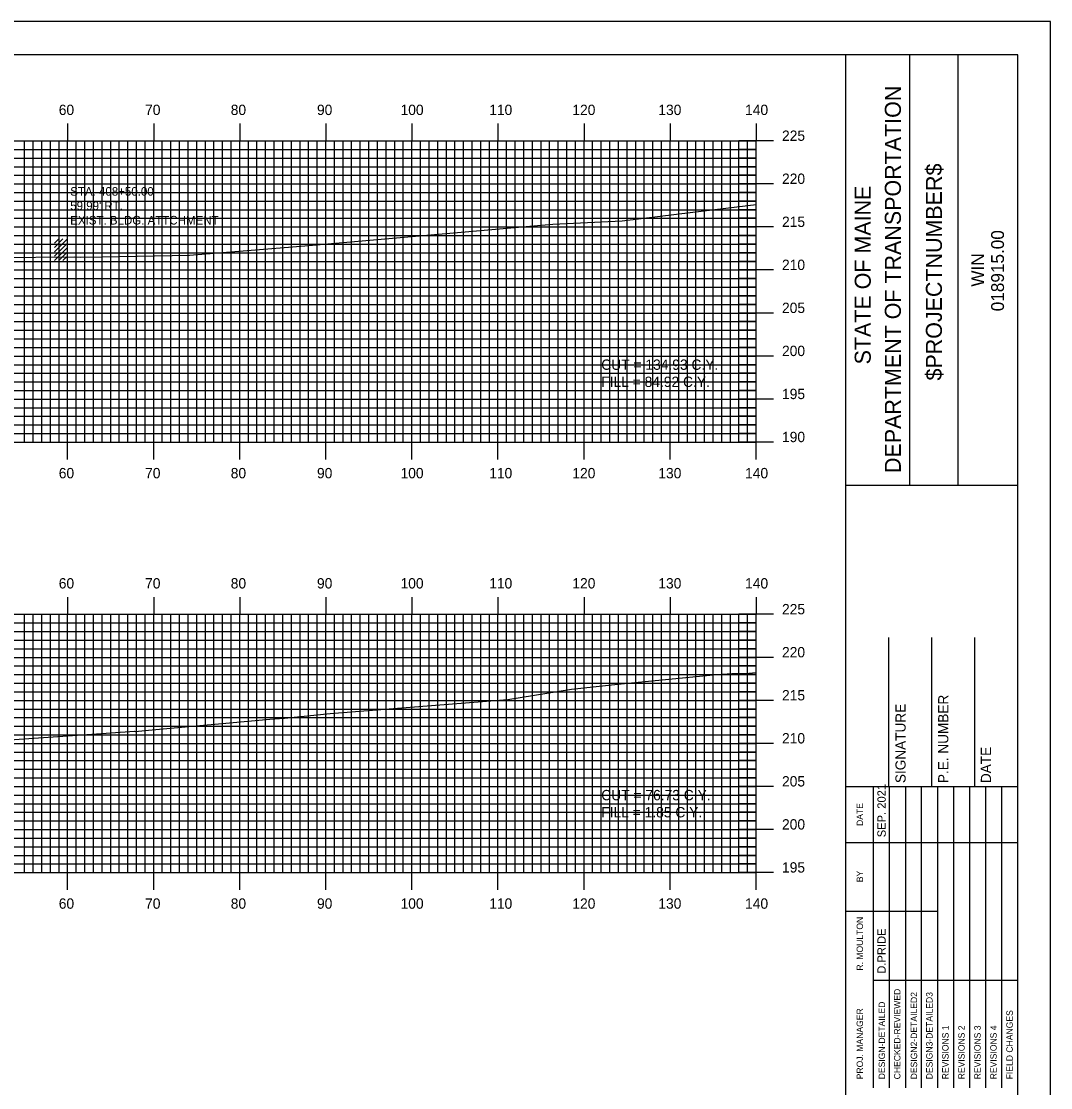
# Model space of a CAD drawing. Extents: x 852529 to 852872, y 364785 to 365005.
# Drawn here: x 852749.3 to 852868.9, y 364881.2 to 365005.1 of the extents above; entities that cross this region are included whole.
import ezdxf

# ---------------------------------------------------------------- set-up
doc = ezdxf.new("R2010")
doc.units = 0
for name, color, linetype in [('BORDER', 7, 'Continuous'), ('D_Text_Monospaced', 7, 'Continuous'), ('D_Text_Standard', 7, 'Continuous'), ('H_V ANNOTATION', 7, 'Continuous'), ('M_Buildings_Attachments', 7, 'Continuous'), ('MAJOR', 7, 'Continuous'), ('MINOR', 7, 'Continuous'), ('PLOT BOUNDARY', 7, 'Continuous'), ('S_Roadway_Centerline', 7, 'Continuous')]:
    doc.layers.add(name, color=color, linetype=linetype)

msp = doc.modelspace()

# ---------------------------------------------------------------- linework, layer by layer
at = {"layer": 'BORDER'}
for p, q in [((852845.13, 364791.23), (852845.13, 365001.23)), ((852852.59, 364951.23), (852852.59, 365001.23)), ((852858.18, 364951.23), (852858.18, 365001.23)), ((852845.13, 364951.22), (852865.13, 364951.22)), ((852850.13, 364916.24), (852850.13, 364933.53)), ((852855.13, 364916.24), (852855.13, 364933.53)), ((852860.13, 364916.24), (852860.13, 364933.53)), ((852845.13, 364916.24), (852865.13, 364916.24))]:
    msp.add_line(p, q, dxfattribs=at)
msp.add_lwpolyline([(852545.13, 364791.23), (852865.13, 364791.23), (852865.13, 365001.23), (852545.13, 365001.23)], close=True, dxfattribs=at)
for points in [[(852848.36, 364909.74), (852848.36, 364916.24)], [(852850.23, 364881.24), (852850.23, 364916.24)], [(852852.09, 364916.24), (852852.09, 364881.24)], [(852853.95, 364881.24), (852853.95, 364916.24)], [(852855.82, 364881.24), (852855.82, 364916.24)], [(852857.68, 364881.24), (852857.68, 364916.24)], [(852859.54, 364881.24), (852859.54, 364916.24)], [(852861.41, 364881.24), (852861.41, 364916.24)], [(852863.27, 364881.24), (852863.27, 364916.24)], [(852848.36, 364881.24), (852848.36, 364914.83)], [(852845.13, 364909.74), (852865.13, 364909.74)], [(852845.13, 364901.74), (852848.36, 364901.74)], [(852848.36, 364901.74), (852855.81, 364901.74)], [(852848.36, 364893.74), (852865.13, 364893.74)]]:
    msp.add_lwpolyline(points, dxfattribs=at)
at = {"layer": 'M_Buildings_Attachments'}
for p, q in [((852753.21, 364978.34), (852754.72, 364979.85)), ((852753.21, 364978.84), (852754.19, 364979.85)), ((852753.21, 364979.33), (852753.7, 364979.85)), ((852753.21, 364977.85), (852754.72, 364979.33)), ((852754.72, 364977.33), (852754.72, 364979.85)), ((852753.21, 364977.33), (852754.72, 364978.84)), ((852753.7, 364977.33), (852754.72, 364978.34)), ((852754.19, 364977.33), (852754.72, 364977.85))]:
    msp.add_line(p, q, dxfattribs=at)
at = {"layer": 'MAJOR'}
for p, q in [((852754.73, 364993.24), (852754.73, 364991.23)), ((852764.73, 364993.24), (852764.73, 364991.23)), ((852774.73, 364993.24), (852774.73, 364991.23)), ((852784.73, 364993.24), (852784.73, 364991.23)), ((852794.73, 364993.24), (852794.73, 364991.23)), ((852804.73, 364993.24), (852804.73, 364991.23)), ((852814.73, 364993.24), (852814.73, 364991.23)), ((852824.73, 364993.24), (852824.73, 364991.23)), ((852834.73, 364993.24), (852834.73, 364991.23)), ((852554.73, 364991.23), (852834.73, 364991.23)), ((852554.73, 364991.23), (852834.73, 364991.23)), ((852754.73, 364956.23), (852754.73, 364991.23)), ((852764.73, 364956.23), (852764.73, 364991.23)), ((852774.73, 364956.23), (852774.73, 364991.23)), ((852784.73, 364956.23), (852784.73, 364991.23)), ((852794.73, 364956.23), (852794.73, 364991.23)), ((852804.73, 364956.23), (852804.73, 364991.23)), ((852814.73, 364956.23), (852814.73, 364991.23)), ((852824.73, 364956.23), (852824.73, 364991.23)), ((852836.73, 364991.23), (852832.73, 364991.23)), ((852834.73, 364956.23), (852834.73, 364991.23)), ((852834.73, 364956.23), (852834.73, 364991.23)), ((852554.73, 364986.23), (852834.73, 364986.23)), ((852836.73, 364986.23), (852832.73, 364986.23)), ((852554.73, 364981.23), (852834.73, 364981.23)), ((852836.73, 364981.23), (852832.73, 364981.23)), ((852554.73, 364976.23), (852834.73, 364976.23)), ((852836.73, 364976.23), (852832.73, 364976.23)), ((852554.73, 364971.23), (852834.73, 364971.23)), ((852836.73, 364971.23), (852832.73, 364971.23)), ((852554.73, 364966.23), (852834.73, 364966.23)), ((852836.73, 364966.23), (852832.73, 364966.23)), ((852554.73, 364961.23), (852834.73, 364961.23)), ((852836.73, 364961.23), (852832.73, 364961.23)), ((852554.73, 364956.23), (852834.73, 364956.23)), ((852554.73, 364956.23), (852834.73, 364956.23)), ((852754.73, 364954.23), (852754.73, 364956.23)), ((852764.73, 364954.23), (852764.73, 364956.23)), ((852774.73, 364954.23), (852774.73, 364956.23)), ((852784.73, 364954.23), (852784.73, 364956.23)), ((852794.73, 364954.23), (852794.73, 364956.23)), ((852804.73, 364954.23), (852804.73, 364956.23)), ((852814.73, 364954.23), (852814.73, 364956.23)), ((852824.73, 364954.23), (852824.73, 364956.23)), ((852836.73, 364956.23), (852832.73, 364956.23)), ((852834.73, 364954.23), (852834.73, 364956.23)), ((852754.73, 364938.24), (852754.73, 364936.23)), ((852764.73, 364938.24), (852764.73, 364936.23)), ((852774.73, 364938.24), (852774.73, 364936.23)), ((852784.73, 364938.24), (852784.73, 364936.23)), ((852794.73, 364938.24), (852794.73, 364936.23)), ((852804.73, 364938.24), (852804.73, 364936.23)), ((852814.73, 364938.24), (852814.73, 364936.23)), ((852824.73, 364938.24), (852824.73, 364936.23)), ((852834.73, 364938.24), (852834.73, 364936.23)), ((852554.73, 364936.23), (852834.73, 364936.23)), ((852554.73, 364936.23), (852834.73, 364936.23)), ((852754.73, 364906.23), (852754.73, 364936.23)), ((852764.73, 364906.23), (852764.73, 364936.23)), ((852774.73, 364906.23), (852774.73, 364936.23)), ((852784.73, 364906.23), (852784.73, 364936.23)), ((852794.73, 364906.23), (852794.73, 364936.23)), ((852804.73, 364906.23), (852804.73, 364936.23)), ((852814.73, 364906.23), (852814.73, 364936.23)), ((852824.73, 364906.23), (852824.73, 364936.23)), ((852836.73, 364936.23), (852832.73, 364936.23)), ((852834.73, 364906.23), (852834.73, 364936.23)), ((852834.73, 364906.23), (852834.73, 364936.23)), ((852554.73, 364931.23), (852834.73, 364931.23)), ((852836.73, 364931.23), (852832.73, 364931.23)), ((852554.73, 364926.23), (852834.73, 364926.23)), ((852836.73, 364926.23), (852832.73, 364926.23)), ((852554.73, 364921.23), (852834.73, 364921.23)), ((852836.73, 364921.23), (852832.73, 364921.23)), ((852554.73, 364916.23), (852834.73, 364916.23)), ((852836.73, 364916.23), (852832.73, 364916.23)), ((852554.73, 364911.23), (852834.73, 364911.23)), ((852836.73, 364911.23), (852832.73, 364911.23)), ((852554.73, 364906.23), (852834.73, 364906.23)), ((852554.73, 364906.23), (852834.73, 364906.23)), ((852754.73, 364904.23), (852754.73, 364906.23)), ((852764.73, 364904.23), (852764.73, 364906.23)), ((852774.73, 364904.23), (852774.73, 364906.23)), ((852784.73, 364904.23), (852784.73, 364906.23)), ((852794.73, 364904.23), (852794.73, 364906.23)), ((852804.73, 364904.23), (852804.73, 364906.23)), ((852814.73, 364904.23), (852814.73, 364906.23)), ((852824.73, 364904.23), (852824.73, 364906.23)), ((852836.73, 364906.23), (852832.73, 364906.23)), ((852834.73, 364904.23), (852834.73, 364906.23))]:
    msp.add_line(p, q, dxfattribs=at)
at = {"layer": 'MINOR'}
for p, q in [((852554.73, 364990.23), (852834.73, 364990.23)), ((852749.73, 364956.23), (852749.73, 364991.23)), ((852750.73, 364956.23), (852750.73, 364991.23)), ((852751.73, 364956.23), (852751.73, 364991.23)), ((852752.73, 364956.23), (852752.73, 364991.23)), ((852753.73, 364956.23), (852753.73, 364991.23)), ((852755.73, 364956.23), (852755.73, 364991.23)), ((852756.73, 364956.23), (852756.73, 364991.23)), ((852757.73, 364956.23), (852757.73, 364991.23)), ((852758.73, 364956.23), (852758.73, 364991.23)), ((852759.73, 364956.23), (852759.73, 364991.23)), ((852760.73, 364956.23), (852760.73, 364991.23)), ((852761.73, 364956.23), (852761.73, 364991.23)), ((852762.73, 364956.23), (852762.73, 364991.23)), ((852763.73, 364956.23), (852763.73, 364991.23)), ((852765.73, 364956.23), (852765.73, 364991.23)), ((852766.73, 364956.23), (852766.73, 364991.23)), ((852767.73, 364956.23), (852767.73, 364991.23)), ((852768.73, 364956.23), (852768.73, 364991.23)), ((852769.73, 364956.23), (852769.73, 364991.23)), ((852770.73, 364956.23), (852770.73, 364991.23)), ((852771.73, 364956.23), (852771.73, 364991.23)), ((852772.73, 364956.23), (852772.73, 364991.23)), ((852773.73, 364956.23), (852773.73, 364991.23)), ((852775.73, 364956.23), (852775.73, 364991.23)), ((852776.73, 364956.23), (852776.73, 364991.23)), ((852777.73, 364956.23), (852777.73, 364991.23)), ((852778.73, 364956.23), (852778.73, 364991.23)), ((852779.73, 364956.23), (852779.73, 364991.23)), ((852780.73, 364956.23), (852780.73, 364991.23)), ((852781.73, 364956.23), (852781.73, 364991.23)), ((852782.73, 364956.23), (852782.73, 364991.23)), ((852783.73, 364956.23), (852783.73, 364991.23)), ((852785.73, 364956.23), (852785.73, 364991.23)), ((852786.73, 364956.23), (852786.73, 364991.23)), ((852787.73, 364956.23), (852787.73, 364991.23)), ((852788.73, 364956.23), (852788.73, 364991.23)), ((852789.73, 364956.23), (852789.73, 364991.23)), ((852790.73, 364956.23), (852790.73, 364991.23)), ((852791.73, 364956.23), (852791.73, 364991.23)), ((852792.73, 364956.23), (852792.73, 364991.23)), ((852793.73, 364956.23), (852793.73, 364991.23)), ((852795.73, 364956.23), (852795.73, 364991.23)), ((852796.73, 364956.23), (852796.73, 364991.23)), ((852797.73, 364956.23), (852797.73, 364991.23)), ((852798.73, 364956.23), (852798.73, 364991.23)), ((852799.73, 364956.23), (852799.73, 364991.23)), ((852800.73, 364956.23), (852800.73, 364991.23)), ((852801.73, 364956.23), (852801.73, 364991.23)), ((852802.73, 364956.23), (852802.73, 364991.23)), ((852803.73, 364956.23), (852803.73, 364991.23)), ((852805.73, 364956.23), (852805.73, 364991.23)), ((852806.73, 364956.23), (852806.73, 364991.23)), ((852807.73, 364956.23), (852807.73, 364991.23)), ((852808.73, 364956.23), (852808.73, 364991.23)), ((852809.73, 364956.23), (852809.73, 364991.23)), ((852810.73, 364956.23), (852810.73, 364991.23)), ((852811.73, 364956.23), (852811.73, 364991.23)), ((852812.73, 364956.23), (852812.73, 364991.23)), ((852813.73, 364956.23), (852813.73, 364991.23)), ((852815.73, 364956.23), (852815.73, 364991.23)), ((852816.73, 364956.23), (852816.73, 364991.23)), ((852817.73, 364956.23), (852817.73, 364991.23)), ((852818.73, 364956.23), (852818.73, 364991.23)), ((852819.73, 364956.23), (852819.73, 364991.23)), ((852820.73, 364956.23), (852820.73, 364991.23)), ((852821.73, 364956.23), (852821.73, 364991.23)), ((852822.73, 364956.23), (852822.73, 364991.23)), ((852823.73, 364956.23), (852823.73, 364991.23)), ((852825.73, 364956.23), (852825.73, 364991.23)), ((852826.73, 364956.23), (852826.73, 364991.23)), ((852827.73, 364956.23), (852827.73, 364991.23)), ((852828.73, 364956.23), (852828.73, 364991.23)), ((852829.73, 364956.23), (852829.73, 364991.23)), ((852830.73, 364956.23), (852830.73, 364991.23)), ((852831.73, 364956.23), (852831.73, 364991.23)), ((852832.73, 364956.23), (852832.73, 364991.23)), ((852834.73, 364990.23), (852832.73, 364990.23)), ((852833.73, 364956.23), (852833.73, 364991.23)), ((852554.73, 364989.23), (852834.73, 364989.23)), ((852834.73, 364989.23), (852832.73, 364989.23)), ((852554.73, 364988.23), (852834.73, 364988.23)), ((852834.73, 364988.23), (852832.73, 364988.23)), ((852554.73, 364987.23), (852834.73, 364987.23)), ((852834.73, 364987.23), (852832.73, 364987.23)), ((852554.73, 364985.23), (852834.73, 364985.23)), ((852834.73, 364985.23), (852832.73, 364985.23)), ((852554.73, 364984.23), (852834.73, 364984.23)), ((852834.73, 364984.23), (852832.73, 364984.23)), ((852554.73, 364983.23), (852834.73, 364983.23)), ((852834.73, 364983.23), (852832.73, 364983.23)), ((852554.73, 364982.23), (852834.73, 364982.23)), ((852834.73, 364982.23), (852832.73, 364982.23)), ((852554.73, 364980.23), (852834.73, 364980.23)), ((852834.73, 364980.23), (852832.73, 364980.23)), ((852554.73, 364979.23), (852834.73, 364979.23)), ((852834.73, 364979.23), (852832.73, 364979.23)), ((852554.73, 364978.23), (852834.73, 364978.23)), ((852834.73, 364978.23), (852832.73, 364978.23)), ((852554.73, 364977.23), (852834.73, 364977.23)), ((852834.73, 364977.23), (852832.73, 364977.23)), ((852554.73, 364975.23), (852834.73, 364975.23)), ((852834.73, 364975.23), (852832.73, 364975.23)), ((852554.73, 364974.23), (852834.73, 364974.23)), ((852834.73, 364974.23), (852832.73, 364974.23)), ((852554.73, 364973.23), (852834.73, 364973.23)), ((852834.73, 364973.23), (852832.73, 364973.23)), ((852554.73, 364972.23), (852834.73, 364972.23)), ((852834.73, 364972.23), (852832.73, 364972.23)), ((852554.73, 364970.23), (852834.73, 364970.23)), ((852834.73, 364970.23), (852832.73, 364970.23)), ((852554.73, 364969.23), (852834.73, 364969.23)), ((852834.73, 364969.23), (852832.73, 364969.23)), ((852554.73, 364968.23), (852834.73, 364968.23)), ((852834.73, 364968.23), (852832.73, 364968.23)), ((852554.73, 364967.23), (852834.73, 364967.23)), ((852834.73, 364967.23), (852832.73, 364967.23)), ((852554.73, 364965.23), (852834.73, 364965.23)), ((852834.73, 364965.23), (852832.73, 364965.23)), ((852554.73, 364964.23), (852834.73, 364964.23)), ((852834.73, 364964.23), (852832.73, 364964.23)), ((852554.73, 364963.23), (852834.73, 364963.23)), ((852834.73, 364963.23), (852832.73, 364963.23)), ((852554.73, 364962.23), (852834.73, 364962.23)), ((852834.73, 364962.23), (852832.73, 364962.23)), ((852554.73, 364960.23), (852834.73, 364960.23)), ((852554.73, 364959.23), (852834.73, 364959.23)), ((852834.73, 364960.23), (852832.73, 364960.23)), ((852834.73, 364959.23), (852832.73, 364959.23)), ((852554.73, 364958.23), (852834.73, 364958.23)), ((852834.73, 364958.23), (852832.73, 364958.23)), ((852554.73, 364957.23), (852834.73, 364957.23)), ((852834.73, 364957.23), (852832.73, 364957.23)), ((852749.73, 364906.23), (852749.73, 364936.23)), ((852750.73, 364906.23), (852750.73, 364936.23)), ((852751.73, 364906.23), (852751.73, 364936.23)), ((852752.73, 364906.23), (852752.73, 364936.23)), ((852753.73, 364906.23), (852753.73, 364936.23)), ((852755.73, 364906.23), (852755.73, 364936.23)), ((852756.73, 364906.23), (852756.73, 364936.23)), ((852757.73, 364906.23), (852757.73, 364936.23)), ((852758.73, 364906.23), (852758.73, 364936.23)), ((852759.73, 364906.23), (852759.73, 364936.23)), ((852760.73, 364906.23), (852760.73, 364936.23)), ((852761.73, 364906.23), (852761.73, 364936.23)), ((852762.73, 364906.23), (852762.73, 364936.23)), ((852763.73, 364906.23), (852763.73, 364936.23)), ((852765.73, 364906.23), (852765.73, 364936.23)), ((852766.73, 364906.23), (852766.73, 364936.23)), ((852767.73, 364906.23), (852767.73, 364936.23)), ((852768.73, 364906.23), (852768.73, 364936.23)), ((852769.73, 364906.23), (852769.73, 364936.23)), ((852770.73, 364906.23), (852770.73, 364936.23)), ((852771.73, 364906.23), (852771.73, 364936.23)), ((852772.73, 364906.23), (852772.73, 364936.23)), ((852773.73, 364906.23), (852773.73, 364936.23)), ((852775.73, 364906.23), (852775.73, 364936.23)), ((852776.73, 364906.23), (852776.73, 364936.23)), ((852777.73, 364906.23), (852777.73, 364936.23)), ((852778.73, 364906.23), (852778.73, 364936.23)), ((852779.73, 364906.23), (852779.73, 364936.23)), ((852780.73, 364906.23), (852780.73, 364936.23)), ((852781.73, 364906.23), (852781.73, 364936.23)), ((852782.73, 364906.23), (852782.73, 364936.23)), ((852783.73, 364906.23), (852783.73, 364936.23)), ((852785.73, 364906.23), (852785.73, 364936.23)), ((852786.73, 364906.23), (852786.73, 364936.23)), ((852787.73, 364906.23), (852787.73, 364936.23)), ((852788.73, 364906.23), (852788.73, 364936.23)), ((852789.73, 364906.23), (852789.73, 364936.23)), ((852790.73, 364906.23), (852790.73, 364936.23)), ((852791.73, 364906.23), (852791.73, 364936.23)), ((852792.73, 364906.23), (852792.73, 364936.23)), ((852793.73, 364906.23), (852793.73, 364936.23)), ((852795.73, 364906.23), (852795.73, 364936.23)), ((852796.73, 364906.23), (852796.73, 364936.23)), ((852797.73, 364906.23), (852797.73, 364936.23)), ((852798.73, 364906.23), (852798.73, 364936.23)), ((852799.73, 364906.23), (852799.73, 364936.23)), ((852800.73, 364906.23), (852800.73, 364936.23)), ((852801.73, 364906.23), (852801.73, 364936.23)), ((852802.73, 364906.23), (852802.73, 364936.23)), ((852803.73, 364906.23), (852803.73, 364936.23)), ((852805.73, 364906.23), (852805.73, 364936.23)), ((852806.73, 364906.23), (852806.73, 364936.23)), ((852807.73, 364906.23), (852807.73, 364936.23)), ((852808.73, 364906.23), (852808.73, 364936.23)), ((852809.73, 364906.23), (852809.73, 364936.23)), ((852810.73, 364906.23), (852810.73, 364936.23)), ((852811.73, 364906.23), (852811.73, 364936.23)), ((852812.73, 364906.23), (852812.73, 364936.23)), ((852813.73, 364906.23), (852813.73, 364936.23)), ((852815.73, 364906.23), (852815.73, 364936.23)), ((852816.73, 364906.23), (852816.73, 364936.23)), ((852817.73, 364906.23), (852817.73, 364936.23)), ((852818.73, 364906.23), (852818.73, 364936.23)), ((852819.73, 364906.23), (852819.73, 364936.23)), ((852820.73, 364906.23), (852820.73, 364936.23)), ((852821.73, 364906.23), (852821.73, 364936.23)), ((852822.73, 364906.23), (852822.73, 364936.23)), ((852823.73, 364906.23), (852823.73, 364936.23)), ((852825.73, 364906.23), (852825.73, 364936.23)), ((852826.73, 364906.23), (852826.73, 364936.23)), ((852827.73, 364906.23), (852827.73, 364936.23)), ((852828.73, 364906.23), (852828.73, 364936.23)), ((852829.73, 364906.23), (852829.73, 364936.23)), ((852830.73, 364906.23), (852830.73, 364936.23)), ((852831.73, 364906.23), (852831.73, 364936.23)), ((852832.73, 364906.23), (852832.73, 364936.23)), ((852833.73, 364906.23), (852833.73, 364936.23)), ((852554.73, 364935.23), (852834.73, 364935.23)), ((852834.73, 364935.23), (852832.73, 364935.23)), ((852554.73, 364934.23), (852834.73, 364934.23)), ((852554.73, 364933.23), (852834.73, 364933.23)), ((852834.73, 364934.23), (852832.73, 364934.23)), ((852834.73, 364933.23), (852832.73, 364933.23)), ((852554.73, 364932.23), (852834.73, 364932.23)), ((852834.73, 364932.23), (852832.73, 364932.23)), ((852554.73, 364930.23), (852834.73, 364930.23)), ((852834.73, 364930.23), (852832.73, 364930.23)), ((852554.73, 364929.23), (852834.73, 364929.23)), ((852554.73, 364928.23), (852834.73, 364928.23)), ((852834.73, 364929.23), (852832.73, 364929.23)), ((852834.73, 364928.23), (852832.73, 364928.23)), ((852554.73, 364927.23), (852834.73, 364927.23)), ((852834.73, 364927.23), (852832.73, 364927.23)), ((852554.73, 364925.23), (852834.73, 364925.23)), ((852834.73, 364925.23), (852832.73, 364925.23)), ((852554.73, 364924.23), (852834.73, 364924.23)), ((852554.73, 364923.23), (852834.73, 364923.23)), ((852834.73, 364924.23), (852832.73, 364924.23)), ((852834.73, 364923.23), (852832.73, 364923.23)), ((852554.73, 364922.23), (852834.73, 364922.23)), ((852834.73, 364922.23), (852832.73, 364922.23)), ((852554.73, 364920.23), (852834.73, 364920.23)), ((852834.73, 364920.23), (852832.73, 364920.23)), ((852554.73, 364919.23), (852834.73, 364919.23)), ((852554.73, 364918.23), (852834.73, 364918.23)), ((852834.73, 364919.23), (852832.73, 364919.23)), ((852834.73, 364918.23), (852832.73, 364918.23)), ((852554.73, 364917.23), (852834.73, 364917.23)), ((852834.73, 364917.23), (852832.73, 364917.23)), ((852554.73, 364915.23), (852834.73, 364915.23)), ((852834.73, 364915.23), (852832.73, 364915.23)), ((852554.73, 364914.23), (852834.73, 364914.23)), ((852554.73, 364913.23), (852834.73, 364913.23)), ((852834.73, 364914.23), (852832.73, 364914.23)), ((852834.73, 364913.23), (852832.73, 364913.23)), ((852554.73, 364912.23), (852834.73, 364912.23)), ((852834.73, 364912.23), (852832.73, 364912.23)), ((852554.73, 364910.23), (852834.73, 364910.23)), ((852834.73, 364910.23), (852832.73, 364910.23)), ((852554.73, 364909.23), (852834.73, 364909.23)), ((852834.73, 364909.23), (852832.73, 364909.23)), ((852554.73, 364908.23), (852834.73, 364908.23)), ((852554.73, 364907.23), (852834.73, 364907.23)), ((852834.73, 364908.23), (852832.73, 364908.23)), ((852834.73, 364907.23), (852832.73, 364907.23))]:
    msp.add_line(p, q, dxfattribs=at)
at = {"layer": 'PLOT BOUNDARY'}
msp.add_lwpolyline([(852528.94, 364785.11), (852868.94, 364785.11), (852868.94, 365005.11), (852528.94, 365005.11)], close=True, dxfattribs=at)
at = {"layer": 'S_Roadway_Centerline'}
for points in [[(852746.5, 364977.68), (852755.5, 364977.76), (852756.28, 364977.7), (852758.75, 364977.77), (852768.9, 364977.94), (852782.27, 364979.04), (852811.1, 364981.54), (852819.15, 364981.94), (852827.38, 364982.93), (852834.73, 364983.84)], [(852746.82, 364921.57), (852757.54, 364922.31), (852762.51, 364922.67), (852762.56, 364922.61), (852764.12, 364922.76), (852778.21, 364924.05), (852779.92, 364924.18), (852785.23, 364924.7), (852796.49, 364925.6), (852805.86, 364926.34), (852813.27, 364927.54), (852818.65, 364928.12), (852829.74, 364929.19), (852831.89, 364929.36), (852833.43, 364929.36), (852834.73, 364929.47)]]:
    msp.add_lwpolyline(points, dxfattribs=at)

# ---------------------------------------------------------------- texts
at = {"layer": 'BORDER'}
for s, height, p in [('DEPARTMENT OF TRANSPORTATION', 1.8635, (852851.54, 364952.64)), ('$PROJECTNUMBER$', 1.8635, (852856.31, 364963.39)), ('STATE OF MAINE', 1.8635, (852848.04, 364965.26)), ('018915.00', 1.491, (852863.52, 364971.43)), ('WIN', 1.491, (852861.2, 364974.29)), ('SIGNATURE', 1.181, (852852.09, 364916.62)), ('P.E. NUMBER', 1.1811, (852857.05, 364916.62)), ('DATE', 1.181, (852862.01, 364916.62)), ('SEP. 2021', 0.969, (852849.78, 364910.33)), ('DATE', 0.743, (852847.14, 364911.65)), ('BY', 0.743, (852847.14, 364905.11)), ('R. MOULTON', 0.745, (852847.14, 364894.84)), ('D.PRIDE', 0.969, (852849.78, 364894.48)), ('CHECKED-REVIEWED', 0.7455, (852851.49, 364882.21)), ('DESIGN2-DETAILED2', 0.7455, (852853.43, 364882.21)), ('DESIGN3-DETAILED3', 0.7455, (852855.22, 364882.21)), ('DESIGN-DETAILED', 0.7455, (852849.7, 364882.21)), ('PROJ. MANAGER', 0.7455, (852847.14, 364882.21)), ('FIELD CHANGES', 0.7455, (852864.54, 364882.21)), ('REVISIONS 1', 0.7455, (852857.08, 364882.21)), ('REVISIONS 2', 0.7455, (852858.95, 364882.21)), ('REVISIONS 3', 0.7455, (852860.81, 364882.21)), ('REVISIONS 4', 0.7455, (852862.67, 364882.21))]:
    msp.add_text(s, height=height, rotation=90, dxfattribs=at).set_placement(p)
at = {"layer": 'D_Text_Monospaced'}
for s, p in [('STA. 408+50.00', (852755.03, 364984.86)), ("59.99' RT.", (852755.03, 364983.19)), ('EXIST. BLDG. ATTCHMENT', (852755.03, 364981.51))]:
    msp.add_text(s, height=1, dxfattribs=at).set_placement(p)
at = {"layer": 'D_Text_Standard'}
for s, p in [('CUT = 134.93 C.Y.', (852816.73, 364964.63)), ('FILL = 84.92 C.Y.', (852816.73, 364962.64)), ('CUT = 76.73 C.Y.', (852816.73, 364914.63)), ('FILL = 1.85 C.Y.', (852816.73, 364912.64))]:
    msp.add_text(s, height=1.2, dxfattribs=at).set_placement(p)
at = {"layer": 'H_V ANNOTATION'}
for s, p in [('60', (852753.7, 364994.23)), ('70', (852763.73, 364994.23)), ('80', (852773.68, 364994.23)), ('90', (852783.7, 364994.23)), ('100', (852793.41, 364994.23)), ('110', (852803.71, 364994.23)), ('120', (852813.37, 364994.23)), ('130', (852823.36, 364994.23)), ('140', (852833.44, 364994.23)), ('225', (852837.73, 364991.23)), ('220', (852837.73, 364986.23)), ('215', (852837.73, 364981.23)), ('210', (852837.73, 364976.23)), ('205', (852837.73, 364971.23)), ('200', (852837.73, 364966.23)), ('195', (852837.73, 364961.23)), ('190', (852837.73, 364956.23)), ('60', (852753.7, 364952.03)), ('70', (852763.73, 364952.03)), ('80', (852773.68, 364952.03)), ('90', (852783.7, 364952.03)), ('100', (852793.41, 364952.03)), ('110', (852803.71, 364952.03)), ('120', (852813.37, 364952.03)), ('130', (852823.36, 364952.03)), ('140', (852833.44, 364952.03)), ('60', (852753.7, 364939.23)), ('70', (852763.73, 364939.23)), ('80', (852773.68, 364939.23)), ('90', (852783.7, 364939.23)), ('100', (852793.41, 364939.23)), ('110', (852803.71, 364939.23)), ('120', (852813.37, 364939.23)), ('130', (852823.36, 364939.23)), ('140', (852833.44, 364939.23)), ('225', (852837.73, 364936.23)), ('220', (852837.73, 364931.23)), ('215', (852837.73, 364926.23)), ('210', (852837.73, 364921.23)), ('205', (852837.73, 364916.23)), ('200', (852837.73, 364911.23)), ('195', (852837.73, 364906.23)), ('60', (852753.7, 364902.03)), ('70', (852763.73, 364902.03)), ('80', (852773.68, 364902.03)), ('90', (852783.7, 364902.03)), ('100', (852793.41, 364902.03)), ('110', (852803.71, 364902.03)), ('120', (852813.37, 364902.03)), ('130', (852823.36, 364902.03)), ('140', (852833.44, 364902.03))]:
    msp.add_text(s, height=1.2, dxfattribs=at).set_placement(p)

doc.saveas('drawing.dxf')
